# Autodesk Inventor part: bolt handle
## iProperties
Created: 2006-04
Part Number: bolt handle
Document SubType Name: Modeling
Designer: Калинин
Author: Калинин
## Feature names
1. Вращение1 [Revolution]
2. Сопряжение1 [Fillet]
3. Сопряжение2 [Fillet]
4. Фаска1 [Chamfer]
